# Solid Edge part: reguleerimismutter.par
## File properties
Author: KULL
Template: Iso Metric Part.par
Last saved by: KULL
Revision: 4
Application: Solid Edge
Accuracy: 0,990
Face Style: Model Default
Fill Style: Normal
Coef. of Thermal Exp: 0.0
Thermal Conductivity: 0.0
Specific Heat: 0.0
Modulus of Elasticity: 0.0
Poisson's Ratio: 0.0
Yield Stress: 0.0
Ultimate Stress: 0.0
Elongation: 0.0
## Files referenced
..\..\Rover_ASM.asm
D:\Solid edge leong\Solid edge Sync practice\ROVER_Heiko_Kull_EKSAM\Vedrustus\Tagumine66tshoob_2.par
QD:\Solid edge leong\Solid edge Sync practice\ROVER_Heiko_Kull_EKSAM\Rover_ASM.asm
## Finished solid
Body 1: sheet body, 1 face, 2 edges, 0 vertices.
  Faces by surface: plane 1
  Edges by curve: circle 2
Body 2: solid body, 53 faces, 109 edges, 58 vertices.
  Faces by surface: cylinder 25, plane 13, torus 13, spline 2
  Edges by curve: circle 63, line 36, spline 6, intersection 4
Bounding box of the edges (mm; curved faces can reach further): 7.400 x 6.924 x 7.706, from (-346.16, 82.0002, 49.5908) to (-338.76, 88.924, 57.297).
Cylindrical faces by radius (mm): R0.1 x12, R0.3 x6, R1.2428 x1, R2 x2, R2.5057 x1, R3 x2, R3.7 x1
Toroidal faces (ring radius, tube radius in mm): R0.2 r0.1 x6, R0.4 r0.1 x6, R3.6 r0.1 x1
Planar faces by outward normal: oblique 13
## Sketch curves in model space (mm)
circle centre (-342.46, 86.3017, 53.2687) radius 2.8
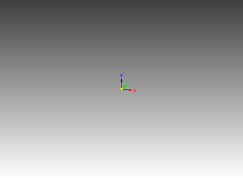
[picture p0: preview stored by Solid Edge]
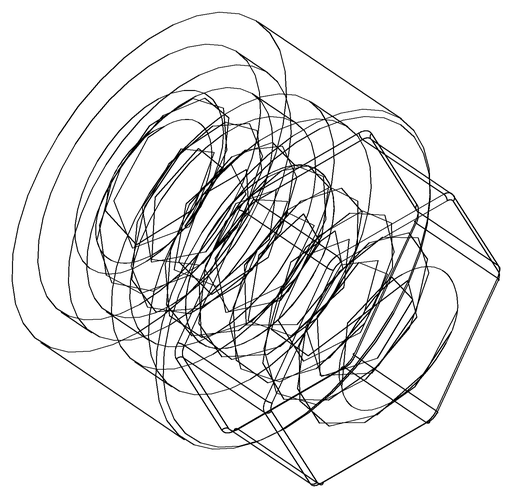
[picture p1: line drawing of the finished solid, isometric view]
